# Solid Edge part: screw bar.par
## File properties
Author: Deepak Maini
Template: Normal.par
Last saved by: Robert a Rhodes jr
Revision: 7
Application: Solid Edge
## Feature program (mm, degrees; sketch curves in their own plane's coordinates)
sketch for "unnamed Protrusion 1" plane through (0, 0, 0) normal (0, 0, 1) x-axis (1, 0, 0)
  circle centre (0, 0) radius 5
extrude "unnamed Protrusion 1" add finite 6 along +normal
sketch for "unnamed Protrusion 2" plane through (0, 0, 0) normal (0, 0, -1) x-axis (1, 0, 0)
  circle centre (0, 0) radius 7
extrude "unnamed Protrusion 2" add finite 24 along +normal
sketch for "unnamed Protrusion 3" plane through (0, 0, -24) normal (0, 0, -1) x-axis (1, 0, 0)
  circle centre (0, 0) radius 8
extrude "unnamed Protrusion 3" add finite 52 along +normal
sketch for "unnamed Protrusion 4" plane through (0, 0, -76) normal (0, 0, -1) x-axis (1, 0, 0)
  circle centre (0, 0) radius 12
extrude "unnamed Protrusion 4" add finite 6 along +normal
sketch for "unnamed Protrusion 5" plane through (0, 0, -82) normal (0, 0, -1) x-axis (1, 0, 0)
  circle centre (0, 0) radius 7
extrude "unnamed Protrusion 5" add finite 8 along +normal
sketch for "unnamed Protrusion 6" plane through (0, 0, -90) normal (0, 0, -1) x-axis (1, 0, 0)
  circle centre (0, 0) radius 8
extrude "unnamed Protrusion 6" add finite 140 along +normal
sketch for "unnamed Protrusion 7" plane through (0, 0, -230) normal (0, 0, -1) x-axis (1, 0, 0)
  circle centre (0, 0) radius 7
extrude "unnamed Protrusion 7" add finite 16 along +normal
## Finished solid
Body 1: solid body, 15 faces, 14 edges, 0 vertices.
  Faces by surface: plane 8, cylinder 7
  Edges by curve: circle 14
Bounding box of the edges (mm): 24.000 x 24.000 x 252.000, from (-12, -12, -246) to (12, 12, 6).
Cylindrical faces by radius (mm): R5 x1, R7 x3, R8 x2, R12 x1
Planar faces by outward normal: +z 5, -z 3
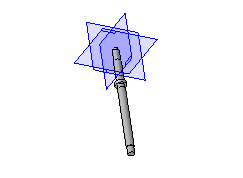
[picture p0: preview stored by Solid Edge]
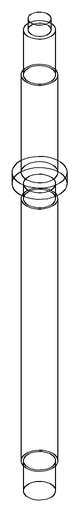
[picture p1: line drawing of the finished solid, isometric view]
